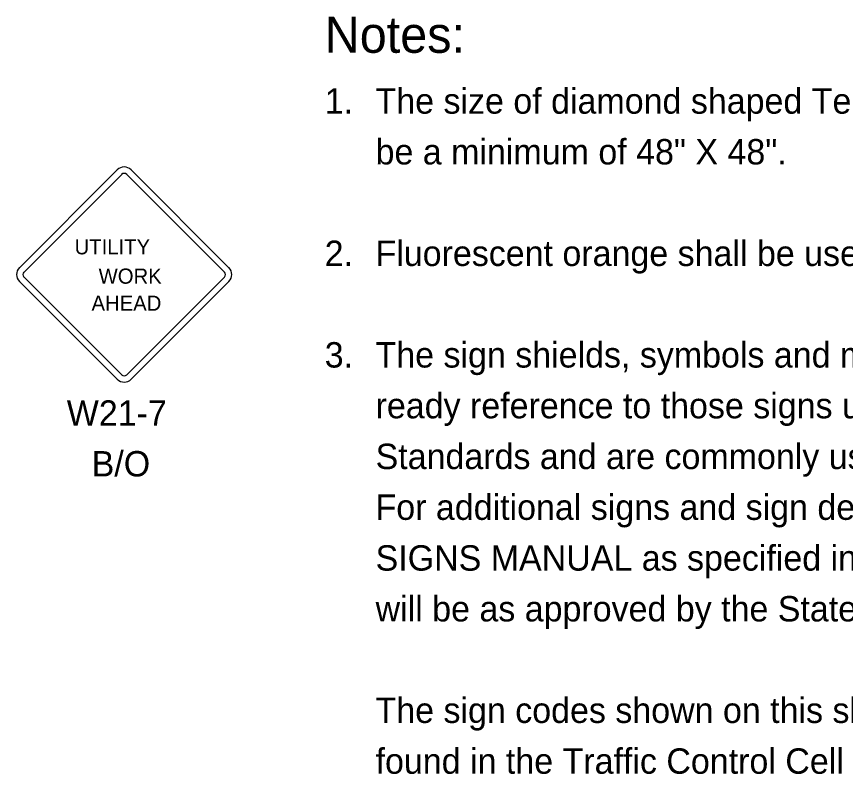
# Model space of a CAD drawing. Extents: x 10000 to 10794, y 10000 to 10499.
# Drawn here: x 10507.5 to 10621.7, y 10164.6 to 10270 of the extents above; entities that cross this region are included whole.
import ezdxf

# ---------------------------------------------------------------- set-up
doc = ezdxf.new("R2010")
doc.units = 0
for name, color, linetype in [('DSText', 7, 'Continuous'), ('DSTitle', 7, 'Continuous'), ('PlotBorder_dp', 7, 'Continuous')]:
    doc.layers.add(name, color=color, linetype=linetype)

msp = doc.modelspace()

# ---------------------------------------------------------------- linework, layer by layer
at = {"layer": 'DSText'}
for p, q in [((10507.86, 10235.41), (10521.34, 10248.89)), ((10523.25, 10248.89), (10536.73, 10235.41)), ((10521.34, 10220.02), (10507.86, 10233.5)), ((10536.73, 10233.5), (10523.25, 10220.02))]:
    msp.add_line(p, q, dxfattribs=at)
for centre, start, end in [((10522.29, 10247.93), 45, 135), ((10508.82, 10234.46), 135, 225), ((10535.76, 10234.46), 315, 45), ((10522.3, 10220.99), 225, 315)]:
    msp.add_arc(centre, 1.36, start, end, dxfattribs=at)
at = {"layer": 'DSTitle'}
for p, q in [((10508.49, 10234.8), (10521.95, 10248.26)), ((10522.64, 10248.26), (10536.1, 10234.8)), ((10521.95, 10220.65), (10508.49, 10234.11)), ((10536.1, 10234.11), (10522.64, 10220.65))]:
    msp.add_line(p, q, dxfattribs=at)
for centre, start, end in [((10522.29, 10247.92), 45, 135), ((10508.83, 10234.46), 135, 225), ((10535.75, 10234.46), 315, 45), ((10522.29, 10221), 225, 315)]:
    msp.add_arc(centre, 0.49, start, end, dxfattribs=at)

# ---------------------------------------------------------------- texts
at = {"layer": 'PlotBorder_dp'}
for s, height, p in [('Notes:', 5, (10549.92, 10265.03)), ('1.', 3.5, (10549.92, 10256.64)), ('The size of diamond shaped Temporary Traffic Control (TTC) warning signs shall ', 3.5, (10556.92, 10256.64)), ('be a minimum of 48" X 48".', 3.5, (10556.93, 10249.64)), ('UTILITY', 2.089, (10515.46, 10237.25)), ('2.', 3.5, (10549.92, 10235.64)), ('Fluorescent orange shall be used for all orange colored work zone signs.', 3.5, (10556.92, 10235.64)), ('WORK', 2.089, (10518.77, 10233.2)), ('AHEAD', 2.089, (10517.79, 10229.47)), ('The sign shields, symbols and messages contained on this sheet are provided for ', 3.5, (10556.92, 10221.64)), ('3.', 3.5, (10549.92, 10221.64)), ('ready reference to those signs used in the development of the 600 series Design ', 3.5, (10556.93, 10214.64)), ('W21-7', 3.5, (10514.38, 10213.62)), ('Standards and are commonly used in the development of traffic control plans.', 3.5, (10556.93, 10207.64)), ('B/O', 3.5, (10517.81, 10206.63)), ('For additional signs and sign detail information refer to the STANDARD HIGHWAY ', 3.5, (10556.92, 10200.64)), ('SIGNS MANUAL as specified in the MUTCD. Special signs for traffic control plans ', 3.5, (10556.93, 10193.64)), ('will be as approved by the State Traffic Plans Engineer.', 3.5, (10556.93, 10186.64)), ('The sign codes shown on this sheet are for the purpose of identifying cell names ', 3.5, (10556.92, 10172.64)), ('found in the Traffic Control Cell Library (TCZ.Cel).', 3.5, (10556.93, 10165.64))]:
    msp.add_text(s, height=height, dxfattribs=at).set_placement(p)

doc.saveas('drawing.dxf')
